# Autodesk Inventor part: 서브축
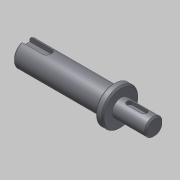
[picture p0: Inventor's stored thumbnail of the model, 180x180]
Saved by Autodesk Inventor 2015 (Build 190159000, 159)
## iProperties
Created: 2018-09
Part Number: 서브축
Document SubType Name: Modeling
Density: 7.86 g/cm^3
Material: 강철, 연강
Appearance: 강철
Mass: 142.801 g
Surface Area: 54.794 cm^2
Volume: 18.1681 cm^3
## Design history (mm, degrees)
sketch "스케치1"
  geometry: L1 (-18.818, -7)-(-18.818, 7) reference; L2 (-41.331, -13.5)-(-41.331, 13.5) reference; L3 (-46.5, 12.249)-(-46.5, -12.249) reference; L4 (-18.331, 0)-(-106.5, 0); L5 (-18.331, 0)-(-18.331, -6); L6 (-18.331, -6)-(-41.331, -6); L7 (-41.331, -12.5)-(-46.5, -12.5); L8 (-46.5, -8.5)-(-106.5, -8.5); L9 (-106.5, -8.5)-(-106.5, 0); L10 (-46.5, -8.5)-(-46.5, -12.5); L11 (-41.331, -6)-(-41.331, -12.5); 2 further points
  constraints: 17 end point, 5 point on line, 3 parallel, 3 perpendicular, 2 collinear, 1 midpoint
  dimensions: "d0" = 23 distance between parallel lines of L2 L5; "d1" = 12 diameter of L6 L4; "d2" = 25 diameter of L7 L4; "d3" = 17 diameter of L8 L4; "d4" = 60 distance of L8.start L8.end
revolve "회전1" sketch "스케치1" stored, may be unused: angle "d5" = 90 deg
chamfer "모따기1" distance "d6" = 1; stored, may be unused: second distance "d7" = 2, angle "d8" = 45 deg
node "작업 평면1"
sketch "스케치2"
  geometry: L1 (11.5, 5)-(11.5, -5) reference; L2 (-5.5, -2)-(4.5, -2); L3 (4.5, 2)-(-5.5, 2); A1 r 2 centre (4.5, 0) between (4.5, -2) and (4.5, 2); A2 r 2 centre (-5.5, 0) between (-5.5, 2) and (-5.5, -2); 2 further points
  constraints: 4 end point, 4 point on circle, 4 tangent, 2 centre point, 1 horizontal alignment, 1 midpoint, 1 parallel, 1 perpendicular
  dimensions: "d9" = 4 distance between parallel lines of L2 L3; "d10" = 14 dimension on A1 A2; "d11" = 5 distance edge to line of A1 L1
extrude "돌출1" cut sketch "스케치2" distance "d12" = 2.5; taper "d13" = 0 deg
node "작업 평면2"
sketch "스케치3"
  geometry: L1 (-30, -7.5)-(-30, 7.5) reference; L2 (-30, 3)-(-15, 3); L3 (-15, -3)-(-30, -3); A1 r 3 centre (-15, 0) between (-15, -3) and (-15, 3); 2 further points
  constraints: 4 end point, 2 perpendicular, 2 point on circle, 2 point on line, 2 tangent, 1 centre point, 1 horizontal alignment, 1 midpoint
  dimensions: "d14" = 6 distance between parallel lines of L3 L2; "d15" = 18 dimension on A1 L1
extrude "돌출2" cut sketch "스케치3" distance "d16" = 3.5; taper "d17" = 0 deg
node "솔리드1"
node "참조1"
node "참조2"
node "참조3"
